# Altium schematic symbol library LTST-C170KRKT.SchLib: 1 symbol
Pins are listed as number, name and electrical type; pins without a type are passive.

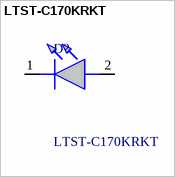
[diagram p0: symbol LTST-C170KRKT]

## LTST-C170KRKT
designator D?
Standard LEDs - SMD Red Clear 631nm; Manufacturer_Name: Lite-On; Geometry.Height: 1.2mm
footprint LEDC2012X120N
pins: 1 K, 2 A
